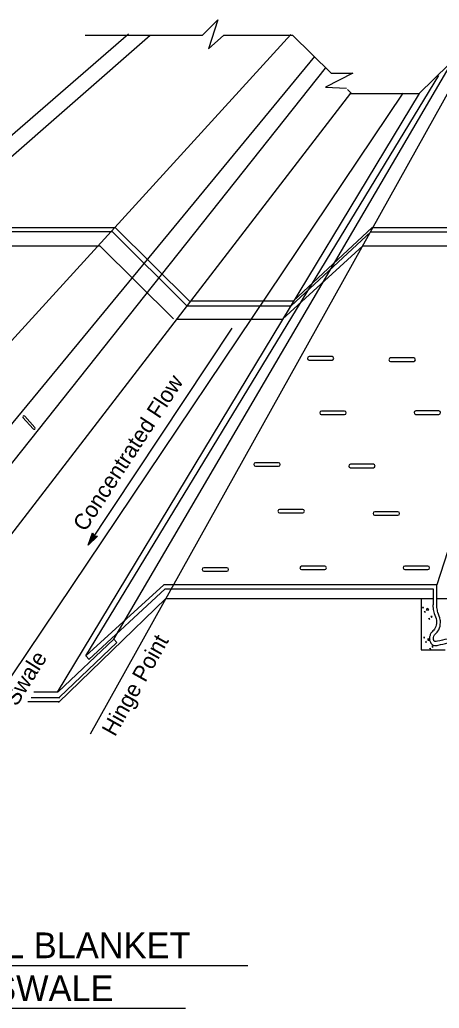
# Model space of a CAD drawing. Extents: x 6712486 to 6713732, y 1869200 to 1869925.
# Drawn here: x 6713312.8 to 6713475.8, y 1869202 to 1869586.3 of the extents above; entities that cross this region are included whole.
import ezdxf

# ---------------------------------------------------------------- set-up
doc = ezdxf.new("R2010")
doc.units = 0
for name, color, linetype in [('56 Stg 3 Anno', 7, 'Continuous'), ('57 Undefined', 7, 'Continuous'), ('60 Nongeo Data', 7, 'Continuous'), ('63 Undefined', 7, 'Continuous')]:
    doc.layers.add(name, color=color, linetype=linetype)

msp = doc.modelspace()

# ---------------------------------------------------------------- linework, layer by layer
at = {"layer": '56 Stg 3 Anno'}
for p, q in [((6713339.31, 1869382), (6713395.27, 1869466.42)), ((6713339.31, 1869382), (6713341.07, 1869386.81)), ((6713339.93, 1869382.98), (6713341.22, 1869386.48)), ((6713341.07, 1869386.81), (6713341.07, 1869386.81)), ((6713341.07, 1869386.81), (6713341.65, 1869385.65)), ((6713342.94, 1869385.6), (6713339.31, 1869382)), ((6713342.6, 1869385.61), (6713339.93, 1869382.97)), ((6713340.55, 1869383.94), (6713341.38, 1869386.2)), ((6713342.24, 1869385.61), (6713340.55, 1869383.94)), ((6713341.17, 1869384.91), (6713341.53, 1869385.87)), ((6713341.92, 1869385.64), (6713341.17, 1869384.91)), ((6713341.65, 1869385.65), (6713342.94, 1869385.6)), ((6713342.94, 1869385.6), (6713342.94, 1869385.6)), ((6713339.31, 1869382), (6713339.31, 1869382))]:
    msp.add_line(p, q, dxfattribs=at)
at = {"layer": '57 Undefined'}
for p, q in [((6713092.76, 1869218.7), (6713401.4, 1869218.7)), ((6713115.97, 1869202.05), (6713377.19, 1869202.05))]:
    msp.add_line(p, q, dxfattribs=at)
at = {"layer": '60 Nongeo Data'}
for p, q in [((6713101.67, 1869361.64), (6713354.99, 1869580.77)), ((6713166.12, 1869304.3), (6713418.14, 1869580.63)), ((6713277.68, 1869505.33), (6713363.47, 1869580.38)), ((6713340.25, 1869308.78), (6713491.7, 1869580.33)), ((6713241.48, 1869346.43), (6713427.47, 1869571.97)), ((6713251.03, 1869340), (6713431.63, 1869567.55)), ((6713349.33, 1869345.55), (6713480.96, 1869570.1)), ((6713338.43, 1869339.02), (6713475.65, 1869564.69)), ((6713262.99, 1869325.95), (6713441.52, 1869557.72)), ((6713282.78, 1869291.27), (6713461.81, 1869557.71)), ((6713327.49, 1869324.95), (6713468.1, 1869557.6)), ((6713441.44, 1869557.62), (6713467.97, 1869557.62)), ((6713519.29, 1869504.18), (6713474.82, 1869366.61)), ((6713377.77, 1869475.13), (6713418.21, 1869475.13)), ((6713379.31, 1869476.98), (6713419.12, 1869476.98)), ((6713373.88, 1869469.9), (6713414.91, 1869469.9)), ((6713425.15, 1869453.98), (6713434.16, 1869453.98)), ((6713434.16, 1869455.35), (6713425.21, 1869455.35)), ((6713456.87, 1869453.45), (6713465.89, 1869453.45)), ((6713465.89, 1869454.83), (6713456.93, 1869454.82)), ((6713429.99, 1869432.83), (6713439.01, 1869432.83)), ((6713439.01, 1869434.2), (6713430.05, 1869434.2)), ((6713466.64, 1869432.91), (6713475.66, 1869432.91)), ((6713475.66, 1869434.28), (6713466.71, 1869434.28)), ((6713314, 1869431.66), (6713317.93, 1869427.24)), ((6713318.61, 1869427.84), (6713314.7, 1869432.23)), ((6713413.36, 1869414.12), (6713404.41, 1869414.12)), ((6713450.22, 1869413.49), (6713441.27, 1869413.49)), ((6713404.35, 1869412.75), (6713413.36, 1869412.75)), ((6713441.21, 1869412.12), (6713450.22, 1869412.12)), ((6713413.72, 1869394.6), (6713422.74, 1869394.6)), ((6713422.74, 1869395.97), (6713413.78, 1869395.97)), ((6713459.72, 1869395.08), (6713450.77, 1869395.07)), ((6713450.71, 1869393.7), (6713459.72, 1869393.7)), ((6713384.26, 1869371.91), (6713393.27, 1869371.91)), ((6713393.27, 1869373.29), (6713384.32, 1869373.28)), ((6713422.27, 1869372.55), (6713431.29, 1869372.55)), ((6713431.29, 1869373.92), (6713422.33, 1869373.91)), ((6713462.39, 1869372.57), (6713471.41, 1869372.57)), ((6713471.41, 1869373.94), (6713462.45, 1869373.94)), ((6713468.92, 1869361.31), (6713473.52, 1869361.3)), ((6713474.73, 1869361.31), (6713493.24, 1869361.31)), ((6713469.62, 1869357.98), (6713469.31, 1869357.84)), ((6713469.31, 1869357.84), (6713469.36, 1869357.9)), ((6713469.36, 1869357.9), (6713469.59, 1869357.56)), ((6713469.59, 1869357.56), (6713469.65, 1869358.01)), ((6713470.33, 1869356.31), (6713470.02, 1869356.16)), ((6713470.02, 1869356.16), (6713470.08, 1869356.22)), ((6713470.08, 1869356.22), (6713470.3, 1869355.88)), ((6713470.3, 1869355.88), (6713470.36, 1869356.33)), ((6713471.35, 1869357.38), (6713470.79, 1869357.21)), ((6713470.9, 1869357.32), (6713470.9, 1869356.76)), ((6713470.9, 1869356.76), (6713471.8, 1869356.87)), ((6713471.8, 1869356.87), (6713471.35, 1869357.38)), ((6713472.01, 1869353.61), (6713471.69, 1869353.47)), ((6713471.69, 1869353.47), (6713471.75, 1869353.53)), ((6713471.75, 1869353.53), (6713471.98, 1869353.19)), ((6713471.98, 1869353.19), (6713472.03, 1869353.64)), ((6713473.05, 1869354.39), (6713472.54, 1869354.39)), ((6713472.59, 1869354.45), (6713472.76, 1869353.94)), ((6713472.76, 1869353.94), (6713473.05, 1869354.39)), ((6713349.33, 1869345.55), (6713350.49, 1869344.21)), ((6713470.07, 1869346.3), (6713469.76, 1869346.16)), ((6713469.76, 1869346.16), (6713469.81, 1869346.22)), ((6713469.81, 1869346.22), (6713470.04, 1869345.88)), ((6713470.04, 1869345.88), (6713470.1, 1869346.33)), ((6713470.78, 1869344.63), (6713470.47, 1869344.49)), ((6713470.47, 1869344.49), (6713470.53, 1869344.54)), ((6713470.53, 1869344.54), (6713470.75, 1869344.2)), ((6713470.75, 1869344.2), (6713470.81, 1869344.65)), ((6713471.8, 1869345.7), (6713471.24, 1869345.53)), ((6713471.35, 1869345.64), (6713471.35, 1869345.08)), ((6713471.35, 1869345.08), (6713472.25, 1869345.19)), ((6713472.25, 1869345.19), (6713471.8, 1869345.7)), ((6713472.45, 1869341.93), (6713472.14, 1869341.79)), ((6713472.14, 1869341.79), (6713472.2, 1869341.85)), ((6713472.2, 1869341.85), (6713472.43, 1869341.51)), ((6713472.43, 1869341.51), (6713472.48, 1869341.96)), ((6713473.49, 1869342.71), (6713472.99, 1869342.71)), ((6713473.04, 1869342.77), (6713473.21, 1869342.26)), ((6713473.21, 1869342.26), (6713473.49, 1869342.71)), ((6713338.43, 1869339.02), (6713339.7, 1869337.64)), ((6713315.93, 1869321.32), (6713327.9, 1869321.32)), ((6713317.22, 1869322.86), (6713328.33, 1869322.86)), ((6713318.18, 1869324.99), (6713327.57, 1869324.99))]:
    msp.add_line(p, q, dxfattribs=at)
for points in [[(6713338.13, 1869580.38), (6713383.84, 1869580.38)], [(6713392.05, 1869580.38), (6713418.81, 1869580.38), (6713433.8, 1869565.48)], [(6713468, 1869557.59), (6713491.27, 1869580.29), (6713514.73, 1869580.29)], [(6713440.12, 1869559.21), (6713441.59, 1869557.75)], [(6713276.29, 1869504.05), (6713348.67, 1869504.05), (6713377.77, 1869475.13)], [(6713277.96, 1869505.59), (6713349.9, 1869505.59), (6713379, 1869476.67)], [(6713418.21, 1869475.13), (6713449.22, 1869503.89), (6713519.04, 1869503.89)], [(6713419.12, 1869476.98), (6713449.8, 1869505.57), (6713519.48, 1869505.57)], [(6713269.81, 1869498.45), (6713343.95, 1869498.45), (6713372.53, 1869470.06)], [(6713414.91, 1869469.9), (6713446.18, 1869498.38), (6713517.29, 1869498.38)], [(6713474.77, 1869366.64), (6713368.73, 1869366.65), (6713338.43, 1869339.02)], [(6713339.64, 1869337.61), (6713369.29, 1869365.11), (6713473.42, 1869365.1), (6713473.44, 1869358.88)], [(6713474.86, 1869358.78), (6713474.82, 1869366.61)], [(6713327.88, 1869320.88), (6713369.52, 1869361.31), (6713468.82, 1869361.33), (6713468.83, 1869341.38), (6713478.14, 1869341.38)], [(6713349.33, 1869345.55), (6713327.72, 1869324.98)], [(6713328.18, 1869322.91), (6713350.49, 1869344.21)]]:
    msp.add_lwpolyline(points, dxfattribs=at)
for centre, radius, start, end in [((6713425.24, 1869454.66), 0.685, 92.5576, 270), ((6713434.16, 1869454.66), 0.686, 270, 90), ((6713456.96, 1869454.14), 0.685, 92.5576, 270), ((6713465.89, 1869454.14), 0.686, 270, 90), ((6713430.08, 1869433.52), 0.685, 92.5576, 270), ((6713439, 1869433.52), 0.686, 270, 90), ((6713466.74, 1869433.6), 0.685, 92.5576, 270), ((6713475.66, 1869433.6), 0.686, 270, 90), ((6713314.38, 1869431.91), 0.45, 44.2481, 221.6905), ((6713318.27, 1869427.54), 0.45, 221.6905, 41.6905), ((6713404.44, 1869413.44), 0.685, 92.5576, 270), ((6713413.36, 1869413.44), 0.686, 270, 90), ((6713441.3, 1869412.81), 0.685, 92.5576, 270), ((6713450.22, 1869412.81), 0.686, 270, 90), ((6713413.81, 1869395.28), 0.685, 92.5576, 270), ((6713422.73, 1869395.28), 0.686, 270, 90), ((6713450.8, 1869394.39), 0.685, 92.5576, 270), ((6713459.72, 1869394.39), 0.686, 270, 90), ((6713384.35, 1869372.6), 0.685, 92.5576, 270), ((6713393.27, 1869372.6), 0.686, 270, 90), ((6713422.36, 1869373.23), 0.685, 92.5576, 270), ((6713431.29, 1869373.23), 0.686, 270, 90), ((6713462.48, 1869373.26), 0.685, 92.5576, 270), ((6713471.4, 1869373.26), 0.686, 270, 90)]:
    msp.add_arc(centre, radius, start, end, dxfattribs=at)
at = {"layer": '63 Undefined'}
for p, q in [((6713383.84, 1869580.38), (6713389.7, 1869586.3)), ((6713389.7, 1869586.3), (6713386.07, 1869574.94)), ((6713386.07, 1869574.94), (6713392.05, 1869580.38)), ((6713442.21, 1869565.59), (6713431.65, 1869560.04)), ((6713433.8, 1869565.48), (6713442.21, 1869565.59)), ((6713431.65, 1869560.04), (6713439.73, 1869559.72))]:
    msp.add_line(p, q, dxfattribs=at)
for points in [[(6713473.33, 1869358.84), (6713473.42, 1869357.59), (6713473.85, 1869355.53), (6713474.72, 1869352.83), (6713474.72, 1869351.63), (6713473.96, 1869349.36), (6713472.77, 1869348.06), (6713472.23, 1869346.98), (6713472.23, 1869344.59), (6713472.55, 1869344), (6713473.02, 1869343.42), (6713473.96, 1869343.08), (6713475.37, 1869343.18), (6713479.16, 1869344.05), (6713481.21, 1869344.27), (6713484.38, 1869343.87), (6713488.77, 1869342.69), (6713490.6, 1869342.73), (6713491.15, 1869343.14), (6713491.27, 1869343.4), (6713491.36, 1869343.79), (6713491.29, 1869344.7), (6713489.99, 1869346.11), (6713489.34, 1869348.71), (6713490.2, 1869350.77), (6713490.85, 1869351.53), (6713490.96, 1869353.13), (6713489.99, 1869354.78), (6713488.04, 1869355.75)], [(6713487.35, 1869354.39), (6713488.9, 1869353.61), (6713489.41, 1869352.76), (6713489.36, 1869352.13), (6713488.89, 1869351.58), (6713487.73, 1869348.83), (6713488.6, 1869345.36), (6713489.13, 1869344.77), (6713489.3, 1869344.63), (6713489.26, 1869344.22), (6713489.1, 1869344.16), (6713488.79, 1869344.2), (6713487.92, 1869344.44), (6713484.67, 1869345.38), (6713481.23, 1869345.8), (6713478.91, 1869345.56), (6713475.14, 1869344.7), (6713474.18, 1869344.62), (6713473.94, 1869344.71), (6713473.82, 1869344.85), (6713473.75, 1869344.98), (6713473.75, 1869346.62), (6713474.04, 1869347.18), (6713475.3, 1869348.57), (6713476.24, 1869351.39), (6713476.24, 1869353.06), (6713475.33, 1869355.92), (6713474.93, 1869357.8), (6713474.86, 1869358.94)]]:
    msp.add_spline(points, degree=3, dxfattribs=at)

# ---------------------------------------------------------------- texts
at = {"layer": '57 Undefined'}
msp.add_text('Concentrated Flow', height=6.2451, rotation=56.8199, dxfattribs=at).set_placement((6713338.25, 1869386.96))
for s, p in [('TEMPORARY EROSION CONTROL BLANKET', (6713095.5, 1869221.5)), ('IN TRAPAZOIDAL DITCH OR SWALE', (6713120.56, 1869204.84))]:
    msp.add_text(s, height=9.9921, dxfattribs=at).set_placement(p)
at = {"layer": '60 Nongeo Data'}
for s, rotation, p in [('Hinge Point', 60.7556, (6713349.76, 1869307.33)), ('Ditch or Swale', 57.8381, (6713294.99, 1869292.77))]:
    msp.add_text(s, height=6.2451, rotation=rotation, dxfattribs=at).set_placement(p)

doc.saveas('drawing.dxf')
